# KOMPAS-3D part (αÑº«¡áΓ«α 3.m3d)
File: created 06.04.2016 12:01:11, last saved 07.04.2016 18:23:13.
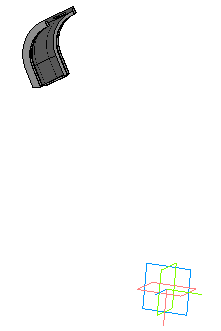
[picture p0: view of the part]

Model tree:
1. Эскиз:1
2. Операция выдавливания:1
     Толщина стенки 1 = 2; Толщина стенки 2 = 6; Расстояние 1 = 1
3. Эскиз:2
4. Операция выдавливания:2
     Толщина стенки 1 = 2; Толщина стенки 2 = 7; Расстояние 1 = 5
5. Эскиз:3
6. Операция выдавливания:3
     Толщина стенки 1 = 2; Толщина стенки 2 = 6; Расстояние 1 = 2
7. Эскиз:4
8. Операция выдавливания:4
     Толщина стенки 1 = 2; Толщина стенки 2 = 2.5; Расстояние 1 = 60
9. Эскиз:5
10. Вырезать элемент выдавливания:1
     Толщина стенки 2 = 1.5; Расстояние 1 = 40
11. Эскиз:6
12. Операция выдавливания:5
     Толщина стенки 1 = 2; Толщина стенки 2 = 2.5; Расстояние 1 = 20
13. Эскиз:7
14. Операция выдавливания:6
     Толщина стенки 1 = 2; Толщина стенки 2 = 6; Расстояние 1 = 2
15. Эскиз:8
16. Операция выдавливания:7
     Толщина стенки 1 = 2; Толщина стенки 2 = 6; Расстояние 1 = 5
17. Эскиз:9
18. Операция выдавливания:8
     Толщина стенки 1 = 2; Толщина стенки 2 = 6; Расстояние 1 = 1
19. Эскиз:10
20. Вырезать элемент выдавливания:2
     Толщина стенки 2 = 1.5; Расстояние 1 = 22
21. Эскиз:11
22. Вырезать элемент выдавливания:3
     Толщина стенки 2 = 1.5; Расстояние 1 = 1
23. Скругление:4
     Радиус = 1
24. Эскиз:12
25. Вырезать элемент выдавливания:4
     Расстояние 1 = 110
26. Эскиз:14
27. Операция выдавливания:10
     Толщина стенки 1 = 6; Расстояние 1 = 0.4; Расстояние 2 = 0.4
